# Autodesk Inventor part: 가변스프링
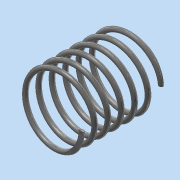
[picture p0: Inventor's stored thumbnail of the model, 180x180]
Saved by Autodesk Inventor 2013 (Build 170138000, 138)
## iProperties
Created: 2018-02
Part Number: 가변스프링
Material: 스테인리스강
Document SubType Name: Modeling
Designer: dgall
Density: 8.08 g/cm^3
Mass: 42.5281 g
Surface Area: 70.8973 cm^2
Volume: 5.26338 cm^3
Author: dgall
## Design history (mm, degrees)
sketch "스케치1"
  geometry: L1 (20, 0)-(0, 0); L2 (0, 0)-(0, 51.25); L3 (0, 51.25)-(20, 51.25); C1 r 1.5 at (20, 0)
  constraints: 6 end point, 1 centre point, 1 coincident, 1 horizontal, 1 parallel, 1 perpendicular, 1 vertical alignment
  dimensions: "d0" = 51.25 distance of L1.end L2.end (derived); "d2" = 40 diameter of L1.start L2; "d3" = 3 diameter of C1
feature "코일1" sketch "스케치1" pitch "d4" = 10; turns "d6" = 6; dims "d5" = 51.25 (= d0), "d7" = 0, angle "d8" = 90 deg, angle "d9" = 90 deg, "d10" = 0, "d11" = 0
node "작업 평면1"
node "작업 평면2"
feature "분할1"
feature "분할2"
node "솔리드1"
other parameters: "d12" = 0, "d13" = 0
